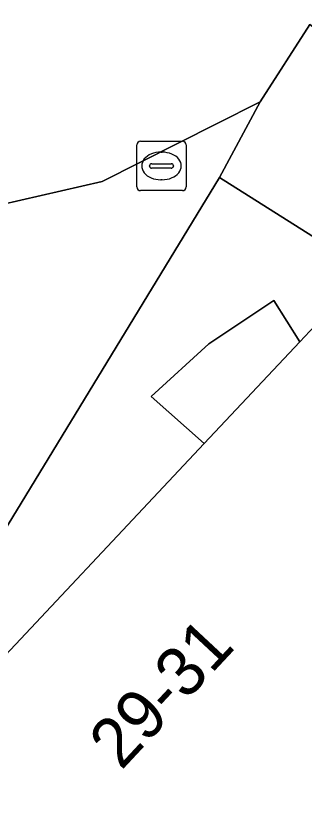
# Model space of a CAD drawing. Extents: x 160663 to 161506, y 382245 to 383291.
# Drawn here: x 161139.44 to 161145.28, y 383110.57 to 383126.73 of the extents above; entities that cross this region are included whole.
import ezdxf

# ---------------------------------------------------------------- set-up
doc = ezdxf.new("R2010")
doc.units = 0
for name, color, linetype in [('IMGEO_Brandkraan', 7, 'Continuous'), ('IMGEO_Pand', 7, 'Continuous'), ('IMGEO_Pand_nummerreeks', 7, 'Continuous'), ('IMGEO_Voetpad_open', 7, 'Continuous'), ('IMGEO_Woonerf_open', 7, 'Continuous')]:
    doc.layers.add(name, color=color, linetype=linetype)

msp = doc.modelspace()

# ---------------------------------------------------------------- linework, layer by layer
at = {"layer": 'IMGEO_Brandkraan'}
for p, q in [((161141.889, 383123.263), (161141.889, 383124.115)), ((161141.964, 383124.189), (161142.816, 383124.189)), ((161142.89, 383124.115), (161142.89, 383123.263)), ((161142.377, 383123.969), (161142.402, 383123.969)), ((161142.148, 383123.683), (161142.148, 383123.695)), ((161142.586, 383123.646), (161142.188, 383123.646)), ((161142.191, 383123.732), (161142.589, 383123.732)), ((161142.632, 383123.695), (161142.632, 383123.683)), ((161142.4, 383123.409), (161142.375, 383123.409)), ((161142.816, 383123.189), (161141.964, 383123.189))]:
    msp.add_line(p, q, dxfattribs=at)
for points in [[(161141.889, 383123.263), (161141.889, 383124.115)], [(161141.964, 383124.189), (161142.816, 383124.189)], [(161142.89, 383124.115), (161142.89, 383123.263)], [(161142.816, 383123.189), (161141.964, 383123.189)]]:
    msp.add_lwpolyline(points, dxfattribs=at)
for centre, radius, start, end in [((161141.966, 383124.113), 0.0765, 91.552, 178.448), ((161141.966, 383124.113), 0.0765, 91.552, 178.448), ((161142.814, 383124.113), 0.0765, 1.552, 88.448), ((161142.814, 383124.113), 0.0765, 1.552, 88.448), ((161142.188, 383123.692), 0.0403, 85.8775, 175.7526), ((161142.185, 383123.682), 0.0366, 178.938, 274.7102), ((161142.589, 383123.689), 0.043, 264.8664, 352.4533), ((161142.593, 383123.694), 0.0386, 1.7309, 96.639), ((161141.966, 383123.265), 0.0765, 181.552, 268.448), ((161141.966, 383123.265), 0.0765, 181.552, 268.448), ((161142.814, 383123.265), 0.0765, 271.552, 358.448), ((161142.814, 383123.265), 0.0765, 271.552, 358.448)]:
    msp.add_arc(centre, radius, start, end, dxfattribs=at)
for centre, major_axis, ratio, start_param, end_param in [((161142.376, 383123.689), (-0.387, 0.002), 0.722429, 4.712389, 7.853982), ((161142.401, 383123.689), (-0.39, 0.002), 0.717154, 1.570796, 4.712389)]:
    msp.add_ellipse(centre, major_axis=major_axis, ratio=ratio, start_param=start_param, end_param=end_param, dxfattribs=at)
at = {"layer": 'IMGEO_Pand'}
msp.add_lwpolyline([(161159.074, 383111.431), (161157.606, 383112.6), (161157.818, 383112.888), (161156.057, 383114.302), (161155.836, 383114.029), (161154.673, 383114.965), (161154.903, 383115.237), (161152.108, 383117.487), (161151.906, 383117.212), (161150.769, 383118.138), (161150.969, 383118.422), (161148.152, 383120.662), (161147.933, 383120.396), (161147.336, 383120.872), (161147.212, 383120.72), (161145.865, 383120.533), (161145.703, 383120.667), (161145.191, 383120.123), (161143.253, 383118.061), (161138.387, 383112.885), (161136.38, 383110.75), (161136.042, 383110.391)], dxfattribs=at)
at = {"layer": 'IMGEO_Voetpad_open'}
for points in [[(161149.062, 383123.775), (161145.902, 383126.174), (161145.396, 383126.558), (161144.392, 383124.992), (161143.565, 383123.455), (161147.439, 383121.008), (161147.336, 383120.872), (161147.933, 383120.396), (161148.152, 383120.662), (161148.237, 383121.062), (161150.798, 383119.84), (161151.618, 383119.236), (161150.969, 383118.422), (161150.769, 383118.138), (161151.906, 383117.212), (161152.108, 383117.487), (161154.903, 383115.237), (161154.673, 383114.965), (161155.836, 383114.029), (161156.057, 383114.302), (161157.818, 383112.888), (161157.606, 383112.6), (161159.074, 383111.431)], [(161128.727, 383097.855), (161128.867, 383098.067), (161130.695, 383100.843), (161132.001, 383103.26), (161135.635, 383109.987), (161135.754, 383110.198), (161135.548, 383110.31), (161135.957, 383110.98), (161135.559, 383111.197), (161136.343, 383112.538), (161137.33, 383113.736), (161137.536, 383113.57), (161143.565, 383123.455), (161144.392, 383124.992), (161143.502, 383124.543), (161141.184, 383123.375), (161139.128, 383122.904), (161137.681, 383120.657), (161129.967, 383109.115), (161130.179, 383108.315), (161124.699, 383099.854)]]:
    msp.add_lwpolyline(points, dxfattribs=at)
for points in [[(161147.336, 383120.872), (161147.439, 383121.008), (161143.565, 383123.455), (161137.536, 383113.57), (161138.387, 383112.885), (161143.253, 383118.061), (161142.181, 383119.018), (161143.352, 383120.082), (161144.667, 383120.963), (161145.191, 383120.123), (161145.703, 383120.667), (161145.865, 383120.533), (161147.212, 383120.72)], [(161143.253, 383118.061), (161145.191, 383120.123), (161144.667, 383120.963), (161143.352, 383120.082), (161142.181, 383119.018)]]:
    msp.add_lwpolyline(points, close=True, dxfattribs=at)
at = {"layer": 'IMGEO_Woonerf_open'}
msp.add_lwpolyline([(161133.469, 383127.948), (161133.773, 383126.361), (161135.448, 383125.333), (161127.679, 383113.208), (161127.839, 383112.186), (161126.716, 383110.439), (161121.278, 383101.982), (161122.257, 383102.231), (161124.53, 383100.761), (161124.699, 383099.854), (161130.179, 383108.315), (161129.967, 383109.115), (161137.681, 383120.657), (161139.128, 383122.904), (161141.184, 383123.375), (161143.502, 383124.543), (161144.392, 383124.992), (161145.396, 383126.558), (161145.902, 383126.174), (161147.93, 383128.951)], dxfattribs=at)

# ---------------------------------------------------------------- texts
at = {"layer": 'IMGEO_Pand_nummerreeks'}
msp.add_text('29-31', height=1, rotation=47.0158, dxfattribs=at).set_placement((161141.573, 383111.421))

doc.saveas('drawing.dxf')
